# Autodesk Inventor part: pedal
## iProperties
Author: hassen
Created: 2000-07
Part Number: pedal
Document SubType Name: Modeling
Designer: hassen
Control State: 0
Master: False
Checked Out: False
PropertySet Name: Design Tracking Control
Shininess: 20.0
PropertySet Name: _Private Model Information
Density: 0.0
Volumn: 0.0
Area: 0.0
PropertySet Name: Model Information
